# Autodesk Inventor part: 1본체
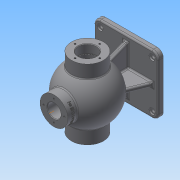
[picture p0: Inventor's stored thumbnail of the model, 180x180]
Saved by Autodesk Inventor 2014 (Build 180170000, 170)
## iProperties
Created: 2017-01
Part Number: 1본체
Material: Generic
Document SubType Name: Modeling
Designer: ksu
Density: 1 g/cm^3
Appearance: Default
Author: ksu
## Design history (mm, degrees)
sketch "Sketch1"
  geometry: L1 (-62.5, 57.5)-(62.5, 57.5); L2 (62.5, 57.5)-(62.5, -57.5); L3 (62.5, -57.5)-(-62.5, -57.5); L4 (-62.5, -57.5)-(-62.5, 57.5); L5 (-62.5, 57.5)-(62.5, -57.5); L6 (62.5, 57.5)-(-62.5, -57.5); 1 further point
  constraints: 12 end point, 2 midpoint, 2 parallel, 1 horizontal, 1 perpendicular
  dimensions: "d0" = 125 distance of L2.end L3.end; "d1" = 115 distance of L1.end L2.end
extrude "Extrusion1" new body sketch "Sketch1" distance "d2" = 10; taper "d3" = 0 deg
fillet "Fillet1" dims "d4" = 12
sketch "Sketch2"
  geometry: A1 r 12 centre (50.5, 45.5) between (62.5, 45.5) and (50.5, 57.5) reference; A2 r 12 centre (-50.5, 45.5) between (-50.5, 57.5) and (-62.5, 45.5) reference; A3 r 12 centre (-50.5, -45.5) between (-62.5, -45.5) and (-50.5, -57.5) reference; A4 r 12 centre (50.5, -45.5) between (50.5, -57.5) and (62.5, -45.5) reference; 5 further points
  constraints: 4 coincident
hole "Hole1" sketch "Sketch2" at (-50.5, 45.5), (50.5, 45.5), (50.5, -45.5), (-50.5, -45.5) diameter "d5" = 8; stored, may be unused: countersink angle "d9" = 90 deg, drill point angle "d11" = 0 deg; dims "d6" = 6, "d7" = 12, "d8" = 3, "d10" = 10
sketch "Sketch3"
  geometry: L1 (57.5, 0)-(-57.5, 0) reference; L2 (-57.5, 0)-(-57.5, 10) reference; L3 (-57.5, 10)-(57.5, 10) reference; L4 (57.5, 10)-(57.5, 0) reference; L5 (0, 0)-(0, 85); L6 (-68, 116)-(-42.988, 116); L7 (-68, 116)-(-68, 85); L8 (68, 116)-(42.988, 116); L9 (68, 116)-(68, 85); L10 (-68, 85)-(68, 85); A1 r 53 centre (0, 85) between (42.988, 116) and (-42.988, 116)
  constraints: 12 end point, 3 perpendicular, 3 symmetric about line, 2 point on circle, 1 centre point
  dimensions: "d14" = 68 horizontal distance of L5.start L6.start; "d15" = 106 diameter of A1; "d16" = 85 distance between parallel lines of L1 L10
revolve "Revolution1" sketch "Sketch3" stored, may be unused: angle "d17" = 90 deg
sketch "Sketch4"
  geometry: L1 (-68, 85)-(68, 85); L2 (-68, 102.5)-(-39.278, 102.5); L3 (-68, 102.5)-(-68, 85); L4 (68, 85)-(68, 102.5); L5 (-68, 85)-(68, 85); L6 (52, 102.5)-(52, 103.5); L7 (52, 103.5)-(50.25, 103.5); L8 (50.25, 103.5)-(50.25, 102.5); L9 (68, 102.5)-(52, 102.5); L10 (50.25, 102.5)-(39.278, 102.5); A1 r 43 centre (0, 85) between (39.278, 102.5) and (-39.278, 102.5); 1 further point
  constraints: 20 end point, 3 perpendicular, 2 point on circle, 1 centre point, 1 parallel
  dimensions: "d19" = 35 diameter of L2 L1; "d22" = 16 distance between parallel lines of L4 L6; "d23" = 37 diameter of L6.end L1; "d24" = 1.75 distance of L6.end L7.end
revolve "Revolution2" sketch "Sketch4" stored, may be unused: angle "d21" = 90 deg
sketch "Sketch5"
  geometry: 1 further point
chamfer "Chamfer1" distance "d27" = 1; stored, may be unused: second distance "d28" = 2, angle "d29" = 45 deg
chamfer "Chamfer2" distance "d30" = 1; stored, may be unused: second distance "d31" = 2, angle "d32" = 45 deg
workplane "Work Plane1"
sketch "Sketch7"
  geometry: C1 r 27 at (0, 0); 1 further point
  constraints: 1 centre point, 1 coincident
  dimensions: "d34" = 54 diameter of C1
extrude "Extrusion2" join sketch "Sketch7" distance "d35" = 30.6375; taper "d36" = 0 deg
sketch "Sketch8"
  geometry: C1 r 27 at (0, 0) reference; C2 r 13 at (0, 0)
  constraints: 1 centre point, 1 coincident
  dimensions: "d37" = 26 diameter of C2
extrude "Extrusion3" cut sketch "Sketch8" distance "d38" = 30.6375; taper "d39" = 0 deg
chamfer "Chamfer3" distance "d40" = 1; stored, may be unused: second distance "d41" = 2, angle "d42" = 45 deg
sketch "Sketch9"
  geometry: L1 (-67, 102.5)-(-68, 103.5) reference; L2 (-68, 103.5)-(-68, 116) reference; L3 (-68, 116)-(-42.988, 116) reference; L4 (-27, 130.607)-(-27, 150) reference; L5 (-27, 150)-(-14, 150) reference; L6 (-14, 150)-(-13, 149) reference; L7 (-13, 149)-(-13, 119.363) reference; L8 (-13, 119.363)-(-25.85, 119.363) reference; L9 (-39.278, 102.5)-(-67, 102.5) reference; L10 (67, 67.5)-(68, 66.5) reference; L11 (68, 66.5)-(68, 54) reference; L12 (68, 54)-(42.988, 54) reference; L13 (-42.988, 54)-(-68, 54) reference; L14 (-68, 54)-(-68, 66.5) reference; L15 (-68, 66.5)-(-67, 67.5) reference; L16 (-67, 67.5)-(-39.278, 67.5) reference; L17 (39.278, 67.5)-(50.25, 67.5) reference; L18 (50.25, 67.5)-(50.25, 66.5) reference; L19 (50.25, 66.5)-(52, 66.5) reference; L20 (52, 66.5)-(52, 67.5) reference; L21 (52, 67.5)-(67, 67.5) reference; L22 (68, 103.5)-(67, 102.5) reference; L23 (67, 102.5)-(52, 102.5) reference; L24 (52, 102.5)-(52, 103.5) reference; L25 (52, 103.5)-(50.25, 103.5) reference; L26 (50.25, 103.5)-(50.25, 102.5) reference; L27 (50.25, 102.5)-(39.278, 102.5) reference; L28 (25.85, 119.363)-(13, 119.363) reference; L29 (13, 119.363)-(13, 149) reference; L30 (13, 149)-(14, 150) reference; L31 (14, 150)-(27, 150) reference; L32 (27, 150)-(27, 130.607) reference; L33 (42.988, 116)-(68, 116) reference; L34 (68, 116)-(68, 103.5) reference; L35 (57.5, 0)-(-57.5, 0) reference; L36 (-57.5, 0)-(-57.5, 10) reference; L37 (-57.5, 10)-(57.5, 10) reference; L38 (57.5, 10)-(57.5, 0) reference; L39 (-43, 85)-(43, 85); L40 (-39.278, 102.5)-(39.278, 102.5); A1 r 53 centre (0, 85) between (-27, 130.607) and (-42.988, 116) reference; A2 r 43 centre (0, 85) between (-25.85, 119.363) and (-39.278, 102.5) reference; A3 r 53 centre (0, 85) between (-42.988, 54) and (42.988, 54) reference; A4 r 43 centre (0, 85) between (-39.278, 67.5) and (39.278, 67.5) reference; A5 r 43 centre (0, 85) between (39.278, 102.5) and (25.85, 119.363) reference; A6 r 53 centre (0, 85) between (42.988, 116) and (27, 130.607) reference; A7 r 43 centre (0, 85) between (39.278, 102.5) and (-39.278, 102.5); 1 further point
  constraints: 5 end point, 2 point on circle, 2 point on line, 1 centre point, 1 coincident, 1 parallel, 1 perpendicular
revolve "Revolution3" sketch "Sketch9" stored, may be unused: angle "d44" = 90 deg
sketch "Sketch11"
  geometry: L1 (47.5, 10)-(33.719, 44.109); L2 (-47.5, 10)-(-33.719, 44.109); L3 (-47.5, 10)-(47.5, 10); L4 (57.5, 10)-(57.5, 0) reference; A1 r 53 centre (0, 85) between (-33.719, 44.109) and (33.719, 44.109); 1 further point
  constraints: 6 end point, 2 point on circle, 1 centre point
extrude "Extrusion4" join sketch "Sketch11" stored distance "d50" = 8; taper "d51" = 0 deg
sketch "Sketch12"
  geometry: L1 (-52.5, 10)-(-37.379, 47.426); L2 (52.5, 10)-(37.379, 47.426); L3 (-52.5, 10)-(52.5, 10); L4 (-50.5, 0)-(50.5, 0) reference; A1 r 53 centre (0, 85) between (-37.379, 47.426) and (37.379, 47.426); 1 further point
  constraints: 6 end point, 2 point on circle, 1 centre point
  dimensions: "d54" = 10 distance between parallel lines of L4 L3
extrude "Extrusion5" join sketch "Sketch12" stored distance "d55" = 8; taper "d56" = 0 deg
workplane "Work Plane2"
sketch "Sketch13"
  geometry: L1 (-20.739, 143.002)-(20.739, 143.002); L2 (20.739, 143.002)-(20.739, 136.998); L3 (20.739, 136.998)-(-20.739, 136.998); L4 (-20.739, 136.998)-(-20.739, 143.002); 1 further point
  constraints: 2 other
emboss "Emboss1" sketch "Sketch13" dims "d59" = 0.5, "d60" = 0
fillet "Fillet2" dims "d61" = 3
fillet "Fillet3" dims "d62" = 3
fillet "Fillet5" dims "d64" = 3
sketch "Sketch14"
  geometry: C1 r 31 at (0, 0) reference; 2 further points
  dimensions: "d65" = 24 distance of C1.centre point (0, -24)
fillet "Fillet6" dims "d66" = 3
fillet "Fillet7" dims "d67" = 3
hole "Hole2" sketch "Sketch14" diameter "d68" = 3.242; stored, may be unused: countersink angle "d72" = 90 deg, drill point angle "d74" = 118 deg; dims "d69" = 16, "d70" = 12, "d71" = 3, "d73" = 19
workaxis "Work Axis1"
pattern_circular "Circular Pattern1" dims angle "d76" = 360 deg
sketch "Sketch15"
  geometry: C1 r 31 at (0, 0) reference; 2 further points
  dimensions: "d78" = 22.5 distance of C1.centre point (0, 22.5)
hole "Hole3" sketch "Sketch15" at (0, 22.5) diameter "d79" = 3.459; stored, may be unused: countersink angle "d83" = 90 deg, drill point angle "d85" = 118 deg; dims "d80" = 12, "d81" = 12, "d82" = 3, "d84" = 15
pattern_circular "Circular Pattern2" dims angle "d87" = 360 deg
sketch "Sketch16"
  geometry: C1 r 27 at (0, 0) reference; 1 further point
  dimensions: "d89" = 20 distance of point (0, 20) C1.centre
hole "Hole4" sketch "Sketch16" at (0, 20) diameter "d90" = 3.459; stored, may be unused: countersink angle "d94" = 90 deg, drill point angle "d96" = 118 deg; dims "d91" = 9, "d92" = 12, "d93" = 3, "d95" = 11
workaxis "Work Axis2"
pattern_circular "Circular Pattern3" dims angle "d98" = 360 deg
body "Solid1"
workaxis "Work Axis3"
workaxis "Work Axis4"
workaxis "Work Axis5"
node "Project Cut Edges1"
node "Project Cut Edges4"
other parameters: "d20" = 35, "d57" = 27.5
